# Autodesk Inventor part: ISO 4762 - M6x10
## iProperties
Created: 2007-08
Part Number: ISO 4762 - M6x10
Material: Stahl, weich, unlegiert
Description: Innensechskantschraube
Vendor: Autodesk Inc.
Document SubType Name: Modeling
Standard: ISO 4762
Designer: Ulrich
Standards Organization: ISO
Language: de-DE
Size Designation: M6 x 10
Categories: <MemberInstance Version="R10.0.0"><Categories><Category DisplayName="Schrauben" InternalName="e4da775c-781d-43d5-af7c-5136215cf5a6" Mnemonic="FSTN"><Category Di
Author: Ulrich
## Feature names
1. Körper [Revolution]
2. Loch [Extrusion]
3. Rundung1 [Fillet]
4. Fase1 [Chamfer]
